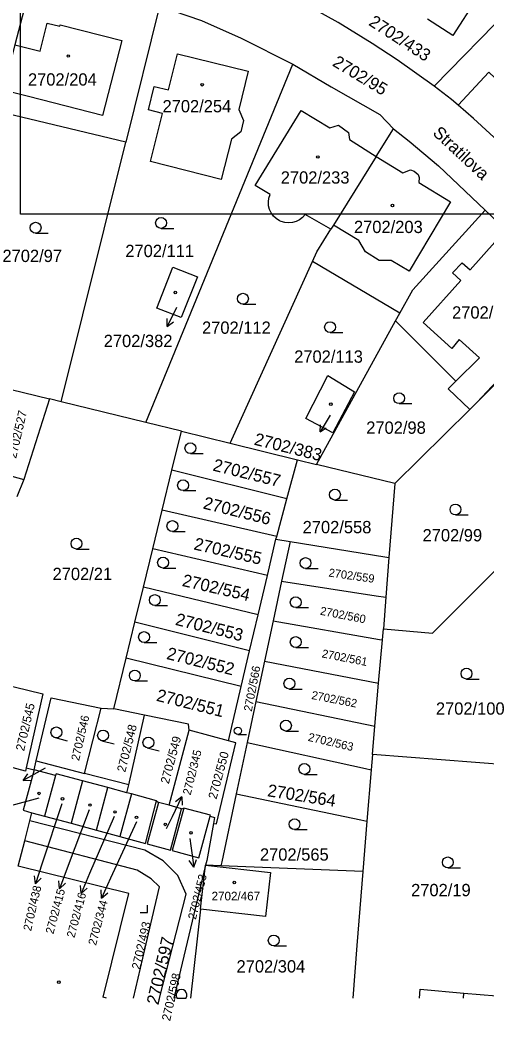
# Model space of a CAD drawing. Extents: x -496682 to -495907, y -1088575 to -1088018.
# Drawn here: x -496557.4 to -496493, y -1088572.6 to -1088434.5 of the extents above; entities that cross this region are included whole.
import ezdxf

# ---------------------------------------------------------------- set-up
doc = ezdxf.new("R2010")
doc.units = 0
for name, color, linetype in [('Hranice parcel', 7, 'Continuous'), ('Parcelní čísla', 7, 'Continuous'), ('Pop  PČ popisy', 7, 'Continuous'), ('Vnitřní kresba', 7, 'Continuous'), ('Vrstva 63', 7, 'Continuous'), ('Značky budov', 7, 'Continuous'), ('Značky kultur', 7, 'Continuous')]:
    doc.layers.add(name, color=color, linetype=linetype)

msp = doc.modelspace()

# ---------------------------------------------------------------- linework, layer by layer
at = {"layer": 'Hranice parcel'}
for p, q in [((-496485.53, -1088428.46), (-496500.3, -1088443.59)), ((-496538.16, -1088432.53), (-496542.82, -1088451.3)), ((-496540.08, -1088490.01), (-496519.8, -1088440.54)), ((-496524.96, -1088457.28), (-496518.62, -1088446.95)), ((-496542.82, -1088451.3), (-496560.5, -1088447.06)), ((-496513.47, -1088448.95), (-496512.11, -1088449.99)), ((-496508.27, -1088453.28), (-496505.89, -1088449.46)), ((-496551.73, -1088487.14), (-496542.82, -1088451.3)), ((-496522.91, -1088458.54), (-496524.96, -1088457.28)), ((-496493.26, -1088460.72), (-496480.12, -1088473.09)), ((-496514.53, -1088463.34), (-496518.09, -1088461.3)), ((-496528.42, -1088492.87), (-496517.08, -1088467.81)), ((-496505.03, -1088474.94), (-496517.08, -1088467.81)), ((-496516.53, -1088495.79), (-496505.61, -1088476)), ((-496505.61, -1088476), (-496505.03, -1088474.94)), ((-496562.76, -1088484.43), (-496553.34, -1088486.74)), ((-496495.38, -1088488.23), (-496498.38, -1088485.38)), ((-496553.34, -1088486.74), (-496556.89, -1088497.88)), ((-496551.73, -1088487.14), (-496553.34, -1088486.74)), ((-496540.08, -1088490.01), (-496551.73, -1088487.14)), ((-496495.38, -1088488.23), (-496505.72, -1088498.45)), ((-496535.15, -1088491.22), (-496540.08, -1088490.01)), ((-496536.46, -1088496.6), (-496535.15, -1088491.22)), ((-496535.15, -1088491.22), (-496528.42, -1088492.87)), ((-496528.42, -1088492.87), (-496519.15, -1088495.15)), ((-496520.6, -1088500.55), (-496519.15, -1088495.15)), ((-496519.15, -1088495.15), (-496516.53, -1088495.79)), ((-496565.8, -1088495.44), (-496556.89, -1088497.88)), ((-496537.8, -1088502.11), (-496536.46, -1088496.6)), ((-496520.6, -1088500.55), (-496536.46, -1088496.6)), ((-496505.72, -1088498.45), (-496516.53, -1088495.79)), ((-496556.89, -1088497.88), (-496557.86, -1088500.28)), ((-496505.72, -1088498.45), (-496506.52, -1088508.66)), ((-496522.01, -1088505.76), (-496520.6, -1088500.55)), ((-496539.1, -1088507.43), (-496537.8, -1088502.11)), ((-496522.01, -1088505.76), (-496537.8, -1088502.11)), ((-496523.29, -1088511.13), (-496522.11, -1088506.13)), ((-496522.11, -1088506.13), (-496522.01, -1088505.76)), ((-496522.11, -1088506.13), (-496520.16, -1088506.45)), ((-496540.39, -1088512.75), (-496539.1, -1088507.43)), ((-496523.29, -1088511.13), (-496539.1, -1088507.43)), ((-496520.16, -1088506.45), (-496521.33, -1088511.93)), ((-496506.52, -1088508.66), (-496506.95, -1088514.12)), ((-496524.57, -1088516.56), (-496523.29, -1088511.13)), ((-496541.56, -1088517.57), (-496540.39, -1088512.75)), ((-496524.57, -1088516.56), (-496540.39, -1088512.75)), ((-496521.33, -1088511.93), (-496522.49, -1088517.38)), ((-496506.95, -1088514.12), (-496507.29, -1088518.51)), ((-496525.75, -1088521.53), (-496524.57, -1088516.56)), ((-496522.49, -1088517.38), (-496523.68, -1088522.94)), ((-496542.77, -1088522.52), (-496541.56, -1088517.57)), ((-496525.75, -1088521.53), (-496541.56, -1088517.57)), ((-496507.42, -1088520.02), (-496507.29, -1088518.51)), ((-496507.95, -1088525.99), (-496507.42, -1088520.02)), ((-496526.9, -1088526.44), (-496525.75, -1088521.53)), ((-496544.48, -1088529.55), (-496542.77, -1088522.52)), ((-496526.9, -1088526.44), (-496542.77, -1088522.52)), ((-496523.68, -1088522.94), (-496524.87, -1088528.52)), ((-496523.68, -1088522.94), (-496507.95, -1088525.99)), ((-496528.68, -1088533.96), (-496526.9, -1088526.44)), ((-496508.46, -1088531.91), (-496507.95, -1088525.99)), ((-496548.52, -1088538.44), (-496546.2, -1088529.44)), ((-496546.2, -1088529.44), (-496544.48, -1088529.55)), ((-496540.23, -1088530.42), (-496544.48, -1088529.55)), ((-496524.87, -1088528.52), (-496526.08, -1088534.17)), ((-496524.87, -1088528.52), (-496508.46, -1088531.91)), ((-496542.41, -1088540.01), (-496540.23, -1088530.42)), ((-496536.84, -1088542.85), (-496534.08, -1088532.5)), ((-496528.68, -1088533.96), (-496534.08, -1088532.5)), ((-496508.81, -1088535.85), (-496508.46, -1088531.91)), ((-496526.08, -1088534.17), (-496527.6, -1088541.29)), ((-496555.46, -1088537.96), (-496555.17, -1088536.73)), ((-496555.17, -1088536.73), (-496548.52, -1088538.44)), ((-496508.81, -1088535.85), (-496508.98, -1088537.97)), ((-496486.91, -1088537.52), (-496508.81, -1088535.85)), ((-496556.58, -1088537.69), (-496555.46, -1088537.96)), ((-496552.5, -1088538.74), (-496555.46, -1088537.96)), ((-496508.98, -1088537.97), (-496509.56, -1088545.05)), ((-496552.5, -1088538.74), (-496554.06, -1088544.33)), ((-496548.78, -1088539.48), (-496550.36, -1088545.33)), ((-496545.3, -1088540.41), (-496548.78, -1088539.48)), ((-496542.41, -1088540.01), (-496548.52, -1088538.44)), ((-496546.88, -1088546.28), (-496545.3, -1088540.41)), ((-496542.66, -1088541.12), (-496545.3, -1088540.41)), ((-496542.66, -1088541.12), (-496542.41, -1088540.01)), ((-496542.04, -1088541.29), (-496543.64, -1088547.15)), ((-496542.04, -1088541.29), (-496542.66, -1088541.12)), ((-496538.59, -1088542.23), (-496542.04, -1088541.29)), ((-496538.59, -1088542.23), (-496538.33, -1088542.45)), ((-496536.84, -1088542.85), (-496538.33, -1088542.45)), ((-496535.12, -1088543.32), (-496536.84, -1088542.85)), ((-496535.12, -1088543.32), (-496534.84, -1088543.23)), ((-496556.76, -1088547.74), (-496556.05, -1088544.98)), ((-496556.05, -1088544.98), (-496555.77, -1088543.87)), ((-496555.77, -1088543.87), (-496554.06, -1088544.33)), ((-496554.06, -1088544.33), (-496550.36, -1088545.33)), ((-496509.56, -1088545.05), (-496510.13, -1088551.97)), ((-496550.36, -1088545.33), (-496546.88, -1088546.28)), ((-496546.88, -1088546.28), (-496543.64, -1088547.15)), ((-496557.65, -1088551.23), (-496556.76, -1088547.74)), ((-496531.82, -1088551.13), (-496536.21, -1088569.45)), ((-496532.51, -1088557.18), (-496531.82, -1088551.13)), ((-496529.72, -1088551.21), (-496531.82, -1088551.13)), ((-496510.13, -1088551.97), (-496529.72, -1088551.21)), ((-496532.51, -1088557.18), (-496533.9, -1088569.45))]:
    msp.add_line(p, q, dxfattribs=at)
for points in [[(-496555.62, -1088428.18), (-496558.12, -1088437.89), (-496559.72, -1088444.15), (-496560.5, -1088447.06)], [(-496497.9, -1088429.23), (-496494.43, -1088431.47), (-496497.73, -1088436.59), (-496501.2, -1088434.35)], [(-496538.16, -1088432.53), (-496532.37, -1088434.53), (-496526.9, -1088436.97), (-496519.8, -1088440.54)], [(-496500.3, -1088443.59), (-496505.39, -1088439.93), (-496508.83, -1088437.68), (-496513.52, -1088434.81), (-496517.03, -1088432.88)], [(-496529.66, -1088456.47), (-496539.44, -1088453.99), (-496537.75, -1088447.35), (-496539.7, -1088446.85), (-496538.9, -1088443.61), (-496536.95, -1088444.09), (-496535.71, -1088439.11), (-496525.94, -1088441.53), (-496527.25, -1088446.79), (-496526.61, -1088448.32), (-496526.96, -1088449.87), (-496528.25, -1088450.89), (-496529.66, -1088456.47)], [(-496519.8, -1088440.54), (-496514.5, -1088443.66), (-496507.77, -1088447.5), (-496505.89, -1088449.46)], [(-496497, -1088446.21), (-496492.75, -1088441.67), (-496485.37, -1088448.58), (-496478.75, -1088441.43), (-496475.55, -1088443.98)], [(-496497, -1088446.21), (-496497.89, -1088445.44), (-496500.3, -1088443.59)], [(-496518.62, -1088446.95), (-496514.7, -1088449.35), (-496513.47, -1088448.95)], [(-496486.71, -1088455.42), (-496490.9, -1088451.69), (-496494.87, -1088448.06), (-496497, -1088446.21)], [(-496505.89, -1088449.46), (-496503.74, -1088451.18), (-496499.69, -1088454.56), (-496493.26, -1088460.72)], [(-496512.11, -1088449.99), (-496511.97, -1088450.97), (-496508.27, -1088453.28)], [(-496508.27, -1088453.28), (-496514.18, -1088462.78), (-496514.53, -1088463.34)], [(-496518.09, -1088461.3), (-496518.44, -1088461.7), (-496518.85, -1088462.02), (-496519.33, -1088462.26), (-496519.83, -1088462.41), (-496520.36, -1088462.46), (-496520.89, -1088462.41), (-496521.39, -1088462.26), (-496521.62, -1088462.16), (-496522.07, -1088461.87), (-496522.45, -1088461.51), (-496522.76, -1088461.08), (-496522.99, -1088460.6), (-496523.12, -1088460.09), (-496523.15, -1088459.56), (-496523.08, -1088459.04), (-496522.91, -1088458.54)], [(-496505.03, -1088474.94), (-496503.24, -1088471.69), (-496493.26, -1088460.72)], [(-496517.08, -1088467.81), (-496516.46, -1088466.44), (-496514.53, -1088463.34)], [(-496538.56, -1088474.21), (-496536.35, -1088468.55), (-496532.92, -1088469.9), (-496535.17, -1088475.53), (-496538.56, -1088474.21)], [(-496480.12, -1088473.09), (-496494.39, -1088487.23), (-496495.38, -1088488.23)], [(-496498.38, -1088485.38), (-496497.3, -1088484.32), (-496505.61, -1088476)], [(-496514.25, -1088491.45), (-496518.01, -1088489.48), (-496514.94, -1088483.51)], [(-496514.94, -1088483.51), (-496511.27, -1088485.78), (-496514.25, -1088491.45)], [(-496507.29, -1088518.51), (-496500.51, -1088519.07), (-496480.76, -1088499.32)], [(-496520.16, -1088506.45), (-496507.08, -1088508.57), (-496506.52, -1088508.66)], [(-496521.33, -1088511.93), (-496508.27, -1088513.92), (-496506.95, -1088514.12)], [(-496522.49, -1088517.38), (-496507.83, -1088519.95), (-496507.42, -1088520.02)], [(-496560.1, -1088526.02), (-496554.29, -1088527.46), (-496556.58, -1088537.69)], [(-496555.17, -1088536.73), (-496553.11, -1088528.01), (-496546.2, -1088529.44)], [(-496534.08, -1088532.5), (-496534.19, -1088531.67), (-496540.23, -1088530.42)], [(-496530.74, -1088545.34), (-496530.3, -1088545.43), (-496527.65, -1088534.24), (-496528.68, -1088533.96)], [(-496526.08, -1088534.17), (-496509.77, -1088537.79), (-496508.98, -1088537.97)], [(-496556.58, -1088537.69), (-496556.68, -1088538.12), (-496563.36, -1088536.35)], [(-496555.46, -1088537.96), (-496556.98, -1088543.54), (-496555.77, -1088543.87)], [(-496548.78, -1088539.48), (-496552.43, -1088538.5), (-496552.5, -1088538.74)], [(-496543.64, -1088547.15), (-496540.12, -1088548.11), (-496538.59, -1088542.23)], [(-496527.6, -1088541.29), (-496529.6, -1088550.65), (-496529.72, -1088551.21)], [(-496527.6, -1088541.29), (-496510.41, -1088544.87), (-496509.56, -1088545.05)], [(-496538.33, -1088542.45), (-496539.88, -1088548.17), (-496536.67, -1088549.04), (-496535.12, -1088543.32)], [(-496534.84, -1088543.23), (-496536.43, -1088549.11), (-496532.74, -1088550.1), (-496531.19, -1088544.37)], [(-496531.19, -1088544.37), (-496531.15, -1088544.22), (-496534.84, -1088543.23)], [(-496538.19, -1088569.45), (-496534.51, -1088555.13), (-496535.64, -1088552.52), (-496537.69, -1088550.53), (-496540.19, -1088549.03), (-496556.05, -1088544.98)], [(-496531.19, -1088544.37), (-496530.59, -1088544.52), (-496530.74, -1088545.34)], [(-496530.74, -1088545.34), (-496531.65, -1088550.49), (-496531.82, -1088551.13)], [(-496541.78, -1088569.45), (-496539.18, -1088558.45), (-496538.17, -1088554.12), (-496539.34, -1088553), (-496541.24, -1088551.8), (-496556.76, -1088547.74)], [(-496545.5, -1088569.45), (-496545.94, -1088569.34), (-496542.39, -1088555.02), (-496557.65, -1088551.23)], [(-496531.82, -1088551.13), (-496522.87, -1088552.14), (-496523.55, -1088558.19), (-496532.51, -1088557.18)], [(-496510.13, -1088551.97), (-496510.95, -1088562.22), (-496511.53, -1088569.45)], [(-496502.29, -1088569.45), (-496502.24, -1088568.24), (-496496.2, -1088568.8), (-496491.67, -1088569.13), (-496489.6, -1088569.29)]]:
    msp.add_lwpolyline(points, dxfattribs=at)
at = {"layer": 'Pop  PČ popisy'}
for p, q in [((-496535.83, -1088474.12), (-496537.12, -1088476.76)), ((-496537.12, -1088476.76), (-496537.13, -1088475.67)), ((-496537.12, -1088476.76), (-496536.25, -1088476.1)), ((-496514.64, -1088489), (-496516.03, -1088491.31)), ((-496516.03, -1088491.31), (-496515.95, -1088490.31)), ((-496516.03, -1088491.31), (-496515.18, -1088490.77)), ((-496554.37, -1088537.96), (-496556.99, -1088539.42)), ((-496553.95, -1088537.73), (-496554.37, -1088537.96)), ((-496556.99, -1088539.42), (-496556.36, -1088538.49)), ((-496556.99, -1088539.42), (-496555.88, -1088539.37)), ((-496555.81, -1088542.14), (-496558.71, -1088542.92)), ((-496554.8, -1088541.88), (-496555.81, -1088542.14)), ((-496536.4, -1088544.39), (-496535.08, -1088541.69)), ((-496535.08, -1088541.69), (-496535.97, -1088542.37)), ((-496535.08, -1088541.69), (-496535.07, -1088542.81)), ((-496551.67, -1088542.64), (-496554.34, -1088550.83)), ((-496547.89, -1088543.46), (-496550.92, -1088551.55)), ((-496544.42, -1088544.4), (-496547.82, -1088552.26)), ((-496537.2, -1088546.07), (-496536.4, -1088544.39)), ((-496541.33, -1088545.13), (-496544.92, -1088552.93)), ((-496533.98, -1088547.45), (-496533.85, -1088548.43)), ((-496533.85, -1088548.43), (-496533.43, -1088551.4)), ((-496533.43, -1088551.4), (-496534.07, -1088550.48)), ((-496533.43, -1088551.4), (-496533.08, -1088550.34)), ((-496554.34, -1088550.83), (-496555.27, -1088553.68)), ((-496550.92, -1088551.55), (-496551.95, -1088554.37)), ((-496555.27, -1088553.68), (-496555.43, -1088552.58)), ((-496555.27, -1088553.68), (-496554.48, -1088552.89)), ((-496551.95, -1088554.37), (-496552.07, -1088553.26)), ((-496547.82, -1088552.26), (-496548.99, -1088555.02)), ((-496544.92, -1088552.93), (-496546.19, -1088555.65)), ((-496551.95, -1088554.37), (-496551.13, -1088553.6)), ((-496548.99, -1088555.02), (-496549.06, -1088553.91)), ((-496548.99, -1088555.02), (-496548.14, -1088554.3)), ((-496546.19, -1088555.65), (-496546.22, -1088554.53)), ((-496546.19, -1088555.65), (-496545.31, -1088554.95))]:
    msp.add_line(p, q, dxfattribs=at)
at = {"layer": 'Vnitřní kresba'}
for p, q in [((-496554.65, -1088438.77), (-496553.66, -1088434.88)), ((-496553.66, -1088434.88), (-496551.91, -1088435.31)), ((-496551.91, -1088435.31), (-496551.88, -1088435.14)), ((-496551.88, -1088435.14), (-496543.37, -1088437.28)), ((-496543.37, -1088437.28), (-496546.02, -1088447.65)), ((-496558.12, -1088437.89), (-496554.65, -1088438.77)), ((-496556.25, -1088445.03), (-496559.72, -1088444.15)), ((-496546.02, -1088447.65), (-496556.25, -1088445.03)), ((-496508.27, -1088453.28), (-496504.61, -1088455.57)), ((-496504.61, -1088455.57), (-496503.55, -1088455.12)), ((-496503.55, -1088455.12), (-496503.03, -1088455.34)), ((-496503.03, -1088455.34), (-496502.51, -1088455.76)), ((-496502.51, -1088455.76), (-496502.36, -1088456.2)), ((-496502.36, -1088456.2), (-496502.4, -1088456.88)), ((-496502.4, -1088456.88), (-496498.03, -1088459.53)), ((-496498.03, -1088459.53), (-496503.74, -1088469.11)), ((-496510.68, -1088464.89), (-496514.18, -1088462.78)), ((-496509.77, -1088466.46), (-496510.68, -1088464.89)), ((-496495.33, -1088468.94), (-496491.92, -1088465.12)), ((-496507.87, -1088467.64), (-496509.77, -1088466.46)), ((-496506.2, -1088467.64), (-496507.87, -1088467.64)), ((-496503.74, -1088469.11), (-496506.2, -1088467.64)), ((-496497.78, -1088469.34), (-496496.42, -1088467.97)), ((-496496.42, -1088467.97), (-496495.33, -1088468.94)), ((-496501.8, -1088476.2), (-496496.63, -1088470.41)), ((-496496.63, -1088470.41), (-496497.78, -1088469.34)), ((-496497.85, -1088479.78), (-496501.8, -1088476.2)), ((-496496.82, -1088478.54), (-496497.85, -1088479.78)), ((-496494.03, -1088481.07), (-496496.82, -1088478.54)), ((-496497.3, -1088484.32), (-496494.03, -1088481.07)), ((-496494.39, -1088487.23), (-496490.92, -1088483.54)), ((-496496.25, -1088569.45), (-496496.2, -1088568.8))]:
    msp.add_line(p, q, dxfattribs=at)
at = {"layer": 'Vrstva 63'}
msp.add_lwpolyline([(-496137.35, -1088164.24), (-496137.35, -1088461.24), (-496557.35, -1088461.24), (-496557.35, -1088164.24)], close=True, dxfattribs=at)
at = {"layer": 'Značky budov'}
for centre in [(-496550.76, -1088439.43), (-496532.29, -1088443.39), (-496516.33, -1088453.36), (-496506.05, -1088460.05), (-496536, -1088472.07), (-496514.55, -1088487.48), (-496554.79, -1088541.21), (-496551.56, -1088541.96), (-496547.77, -1088542.81), (-496544.31, -1088543.77), (-496541.35, -1088544.51), (-496537.38, -1088545.49), (-496533.83, -1088546.65), (-496527.86, -1088553.5), (-496552.07, -1088567.27)]:
    msp.add_circle(centre, 0.175, dxfattribs=at)
at = {"layer": 'Značky kultur'}
for p, q in [((-496537.96, -1088463.22), (-496536.21, -1088463.22)), ((-496555.27, -1088463.87), (-496553.52, -1088463.87)), ((-496526.66, -1088473.68), (-496524.91, -1088473.68)), ((-496514.65, -1088477.6), (-496512.9, -1088477.6)), ((-496505.12, -1088487.41), (-496503.37, -1088487.41)), ((-496533.92, -1088494.31), (-496532.17, -1088494.31)), ((-496534.93, -1088499.42), (-496533.18, -1088499.42)), ((-496513.98, -1088500.71), (-496512.23, -1088500.71)), ((-496497.35, -1088502.77), (-496495.6, -1088502.77)), ((-496536.4, -1088505.06), (-496534.65, -1088505.06)), ((-496549.63, -1088507.48), (-496547.88, -1088507.48)), ((-496537.68, -1088510.1), (-496535.93, -1088510.1)), ((-496518.03, -1088510.16), (-496516.28, -1088510.16)), ((-496538.82, -1088515.27), (-496537.07, -1088515.27)), ((-496519.39, -1088515.57), (-496517.64, -1088515.57)), ((-496540.3, -1088520.38), (-496538.55, -1088520.38)), ((-496519.39, -1088521.07), (-496517.64, -1088521.07)), ((-496541.58, -1088525.69), (-496539.83, -1088525.69)), ((-496495.83, -1088525.42), (-496494.08, -1088525.42)), ((-496520.26, -1088526.8), (-496518.51, -1088526.8)), ((-496520.74, -1088532.6), (-496518.99, -1088532.6)), ((-496552.58, -1088533.51), (-496550.89, -1088533.94)), ((-496546.14, -1088533.94), (-496544.45, -1088534.36)), ((-496527.35, -1088533.07), (-496526.18, -1088533.07)), ((-496539.89, -1088534.93), (-496538.2, -1088535.35)), ((-496518.19, -1088538.58), (-496516.44, -1088538.58)), ((-496519.55, -1088546.21), (-496517.8, -1088546.21)), ((-496498.41, -1088551.48), (-496496.66, -1088551.48)), ((-496539.85, -1088557.64), (-496539.85, -1088556.64)), ((-496540.85, -1088557.64), (-496539.85, -1088557.64)), ((-496522.42, -1088562.26), (-496520.67, -1088562.26)), ((-496535.77, -1088569.45), (-496534.52, -1088569.45))]:
    msp.add_line(p, q, dxfattribs=at)
for centre, radius in [((-496537.96, -1088462.47), 0.75), ((-496555.27, -1088463.12), 0.75), ((-496526.66, -1088472.93), 0.75), ((-496514.65, -1088476.85), 0.75), ((-496505.12, -1088486.66), 0.75), ((-496533.92, -1088493.56), 0.75), ((-496534.93, -1088498.67), 0.75), ((-496513.98, -1088499.96), 0.75), ((-496497.35, -1088502.02), 0.75), ((-496536.4, -1088504.31), 0.75), ((-496549.63, -1088506.73), 0.75), ((-496537.68, -1088509.35), 0.75), ((-496518.03, -1088509.41), 0.75), ((-496538.82, -1088514.52), 0.75), ((-496519.39, -1088514.82), 0.75), ((-496540.3, -1088519.63), 0.75), ((-496519.39, -1088520.32), 0.75), ((-496541.58, -1088524.94), 0.75), ((-496495.83, -1088524.67), 0.75), ((-496520.26, -1088526.05), 0.75), ((-496520.74, -1088531.85), 0.75), ((-496552.4, -1088532.78), 0.75), ((-496545.96, -1088533.21), 0.75), ((-496527.36, -1088532.57), 0.502), ((-496539.71, -1088534.2), 0.75), ((-496518.19, -1088537.83), 0.75), ((-496519.55, -1088545.46), 0.75), ((-496498.41, -1088550.73), 0.75), ((-496522.42, -1088561.51), 0.75)]:
    msp.add_circle(centre, radius, dxfattribs=at)
msp.add_arc((-496535.14, -1088569.03), 0.75, 326.0818, 213.9182, dxfattribs=at)

# ---------------------------------------------------------------- texts
at = {"layer": 'Parcelní čísla'}
for s, height, rotation, p in [('2702/433', 1.7, 327, (-496509.44, -1088435.09)), ('2702/95', 1.7, 329, (-496514.44, -1088440.7)), ('2702/527', 1.2, 77, (-496557.95, -1088495.03)), ('2702/383', 1.7, 346, (-496525.22, -1088493.06)), ('2702/557', 1.7, 346, (-496530.92, -1088496.63)), ('2702/556', 1.7, 346, (-496532.26, -1088501.87)), ('2702/555', 1.7, 347, (-496533.54, -1088507.52)), ('2702/559', 1.139, 352, (-496514.9, -1088511.27)), ('2702/554', 1.7, 347, (-496535.15, -1088512.56)), ('2702/560', 1.139, 349, (-496516.09, -1088516.53)), ('2702/553', 1.7, 346, (-496536.09, -1088517.93)), ('2702/552', 1.7, 346, (-496537.3, -1088522.64)), ('2702/561', 1.139, 349, (-496515.85, -1088522.42)), ('2702/566', 1.139, 79, (-496525.45, -1088529.96)), ('2702/551', 1.7, 346, (-496538.71, -1088528.41)), ('2702/562', 1.139, 349, (-496517.28, -1088528.16)), ('2702/545', 1.2, 77, (-496556.86, -1088535.43)), ('2702/546', 1.139, 77, (-496549.27, -1088536.77)), ('2702/548', 1.2, 76, (-496542.9, -1088538.36)), ('2702/549', 1.2, 75, (-496536.9, -1088539.97)), ('2702/563', 1.139, 347, (-496517.76, -1088533.94)), ('2702/345', 1.139, 76, (-496533.89, -1088541.52)), ('2702/550', 1.2, 75, (-496530.32, -1088542.09)), ('2702/564', 1.7, 351, (-496523.37, -1088541.59)), ('2702/453', 1.139, 76, (-496533.17, -1088558.69)), ('2702/438', 1.139, 77, (-496555.89, -1088560.27)), ('2702/415', 1.139, 75, (-496552.82, -1088560.69)), ('2702/416', 1.139, 75, (-496549.91, -1088561.21)), ('2702/344', 1.139, 75, (-496546.94, -1088562.27)), ('2702/493', 1.2, 77, (-496540.87, -1088565.59)), ('2702/597', 1.7, 77, (-496538.33, -1088570.49)), ('2702/598', 1.2, 77, (-496536.72, -1088572.7))]:
    msp.add_text(s, height=height, rotation=rotation, dxfattribs=at).set_placement(p)
for s, height, p in [('2702/204', 1.7, (-496556.32, -1088443.51)), ('2702/254', 1.7, (-496537.76, -1088447.2)), ('2702/233', 1.7, (-496521.45, -1088457.04)), ('2702/203', 1.7, (-496511.35, -1088463.86)), ('2702/97', 1.7, (-496559.84, -1088467.86)), ('2702/111', 1.7, (-496542.89, -1088467.18)), ('2702/202', 1.7, (-496497.82, -1088475.67)), ('2702/112', 1.7, (-496532.31, -1088477.77)), ('2702/382', 1.7, (-496545.87, -1088479.6)), ('2702/113', 1.7, (-496519.6, -1088481.76)), ('2702/98', 1.7, (-496509.66, -1088491.57)), ('2702/558', 1.7, (-496518.43, -1088505.3)), ('2702/99', 1.7, (-496501.89, -1088506.42)), ('2702/21', 1.7, (-496552.93, -1088511.76)), ('2702/100', 1.7, (-496500.05, -1088530.34)), ('2702/565', 1.7, (-496524.32, -1088550.49)), ('2702/467', 1.2, (-496530.99, -1088555.98)), ('2702/19', 1.7, (-496503.47, -1088555.4)), ('2702/304', 1.7, (-496527.55, -1088565.93))]:
    msp.add_text(s, height=height, dxfattribs=at).set_placement(p)
at = {"layer": 'Pop  PČ popisy'}
msp.add_text('Stratilova', height=1.7, rotation=317, dxfattribs=at).set_placement((-496500.6, -1088450.19))

doc.saveas('drawing.dxf')
